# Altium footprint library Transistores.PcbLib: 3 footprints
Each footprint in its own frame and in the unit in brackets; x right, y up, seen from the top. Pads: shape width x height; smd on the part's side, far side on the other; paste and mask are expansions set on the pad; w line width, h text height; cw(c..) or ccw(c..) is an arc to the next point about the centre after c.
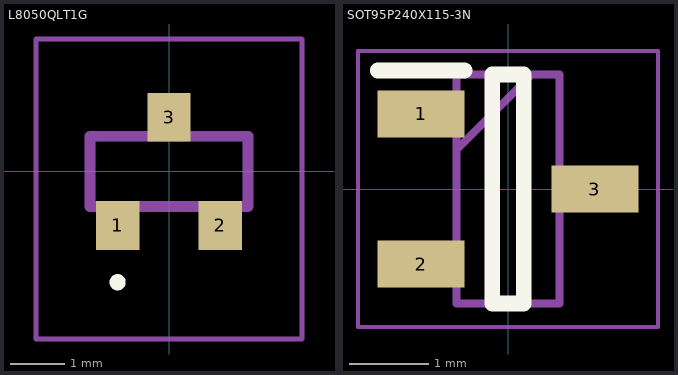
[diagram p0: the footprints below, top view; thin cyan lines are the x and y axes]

## L8050QLT1G [mm]
pads (3):
  rect 0.8x0.9 smd: 1(-0.95,-1) 2(0.95,-1) 3(0,1)
Top Overlay:
  lines w0.2: -0.95,-2.1 cw(c-0.95,-2.05) -0.95,-2 ; -0.95,-2.1 ccw(c-0.95,-2.05) -0.95,-2 ; -0.95,-2.1 cw(c-0.95,-2.05) -0.95,-2
Mechanical 13:
  lines w0.2: -1.46,-0.65 -1.46,0.65 1.46,0.65 1.46,-0.65 -1.46,-0.65
Mechanical 15:
  lines w0.1: -2.46,-3.1 -2.46,2.45 2.46,2.45 2.46,-3.1 -2.46,-3.1
3D body "L8050QLT1G.stp": height 1.21, standoff 0, extent -1.46,-0.65 1.46,0.65

## PCBComponent_1 [mm]

## SOT95P240X115-3N [mm]
pads (3):
  rect 1.1x0.6 smd: 1(-1.1,0.95) 2(-1.1,-0.95) 3(1.1,0)
Top Overlay:
  lines w0.2: -1.65,1.5 -0.55,1.5 ; -0.2,-1.45 -0.2,1.45 0.2,1.45 0.2,-1.45 -0.2,-1.45
Mechanical 13:
  lines w0.1: -0.65,0.5 0.3,1.45 ; -0.65,-1.45 -0.65,1.45 0.65,1.45 0.65,-1.45 -0.65,-1.45
Mechanical 15:
  lines w0.05: -1.9,-1.75 -1.9,1.75 1.9,1.75 1.9,-1.75 -1.9,-1.75
3D body "SS8050-G.stp": height 1.15, standoff 0, extent -1.2,-1.45 1.2,1.45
